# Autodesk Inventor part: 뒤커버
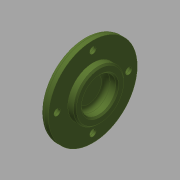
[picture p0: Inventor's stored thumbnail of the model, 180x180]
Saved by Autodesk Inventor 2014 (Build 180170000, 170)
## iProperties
Created: 2015-12
Part Number: 뒤커버
Document SubType Name: Modeling
Designer: mdu
Density: 2.71 g/cm^3
Material: 알루미늄 6061
Appearance: 알루미늄 - 평지
Author: mdu
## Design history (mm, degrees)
sketch "스케치1"
  geometry: L1 (-7, 0)-(7, 0); L2 (-7, 0)-(-7, 15.539); L3 (-7, 15.539)-(-4, 18.5); L4 (-4, 18.5)-(-4, 31); L5 (-4, 31)-(2, 31); L6 (2, 31)-(2, 17.5); L7 (2, 17.5)-(7, 17.5); L8 (7, 17.5)-(7, 0); 2 further points
  constraints: 16 end point, 4 parallel, 2 perpendicular, 1 coincident, 1 horizontal, 1 midpoint
  dimensions: "d0" = 14 distance of L1.start L1.end; "d1" = 62 diameter of L5 L1; "d2" = 35 diameter of L7 L1; "d3" = 37 diameter of L3.end L1; "d4" = 3 distance between parallel lines of L4 L2; "d5" = 6 distance of L4.end L5.end
revolve "회전1" sketch "스케치1" stored, may be unused: angle "d6" = 90 deg
sketch "스케치2" dims "d32" = 50
  geometry: 3 further points
  constraints: 2 vertical alignment, 1 coincident, 2 other
hole "구멍1" sketch "스케치2" at (0, 25) diameter "d8" = 4.5; stored, may be unused: countersink angle "d12" = 90 deg, drill point angle "d14" = 118 deg; dims "d9" = 6, "d10" = 8, "d11" = 4.4, "d13" = 8
hole "구멍2" diameter "d20" = 24; stored, may be unused: countersink angle "d24" = 90 deg, drill point angle "d26" = 0 deg; dims "d18" = 10, "d19" = 10, "d21" = 6, "d22" = 8, "d23" = 4.4, "d25" = 8
fillet "모깎기1" dims "d27" = 3
fillet "모깎기2" dims "d28" = 3
chamfer "모따기1" distance "d29" = 1; stored, may be unused: second distance "d30" = 2, angle "d31" = 45 deg
node "솔리드1"
pattern_circular "원형 패턴1" dims angle "d16" = 360 deg
